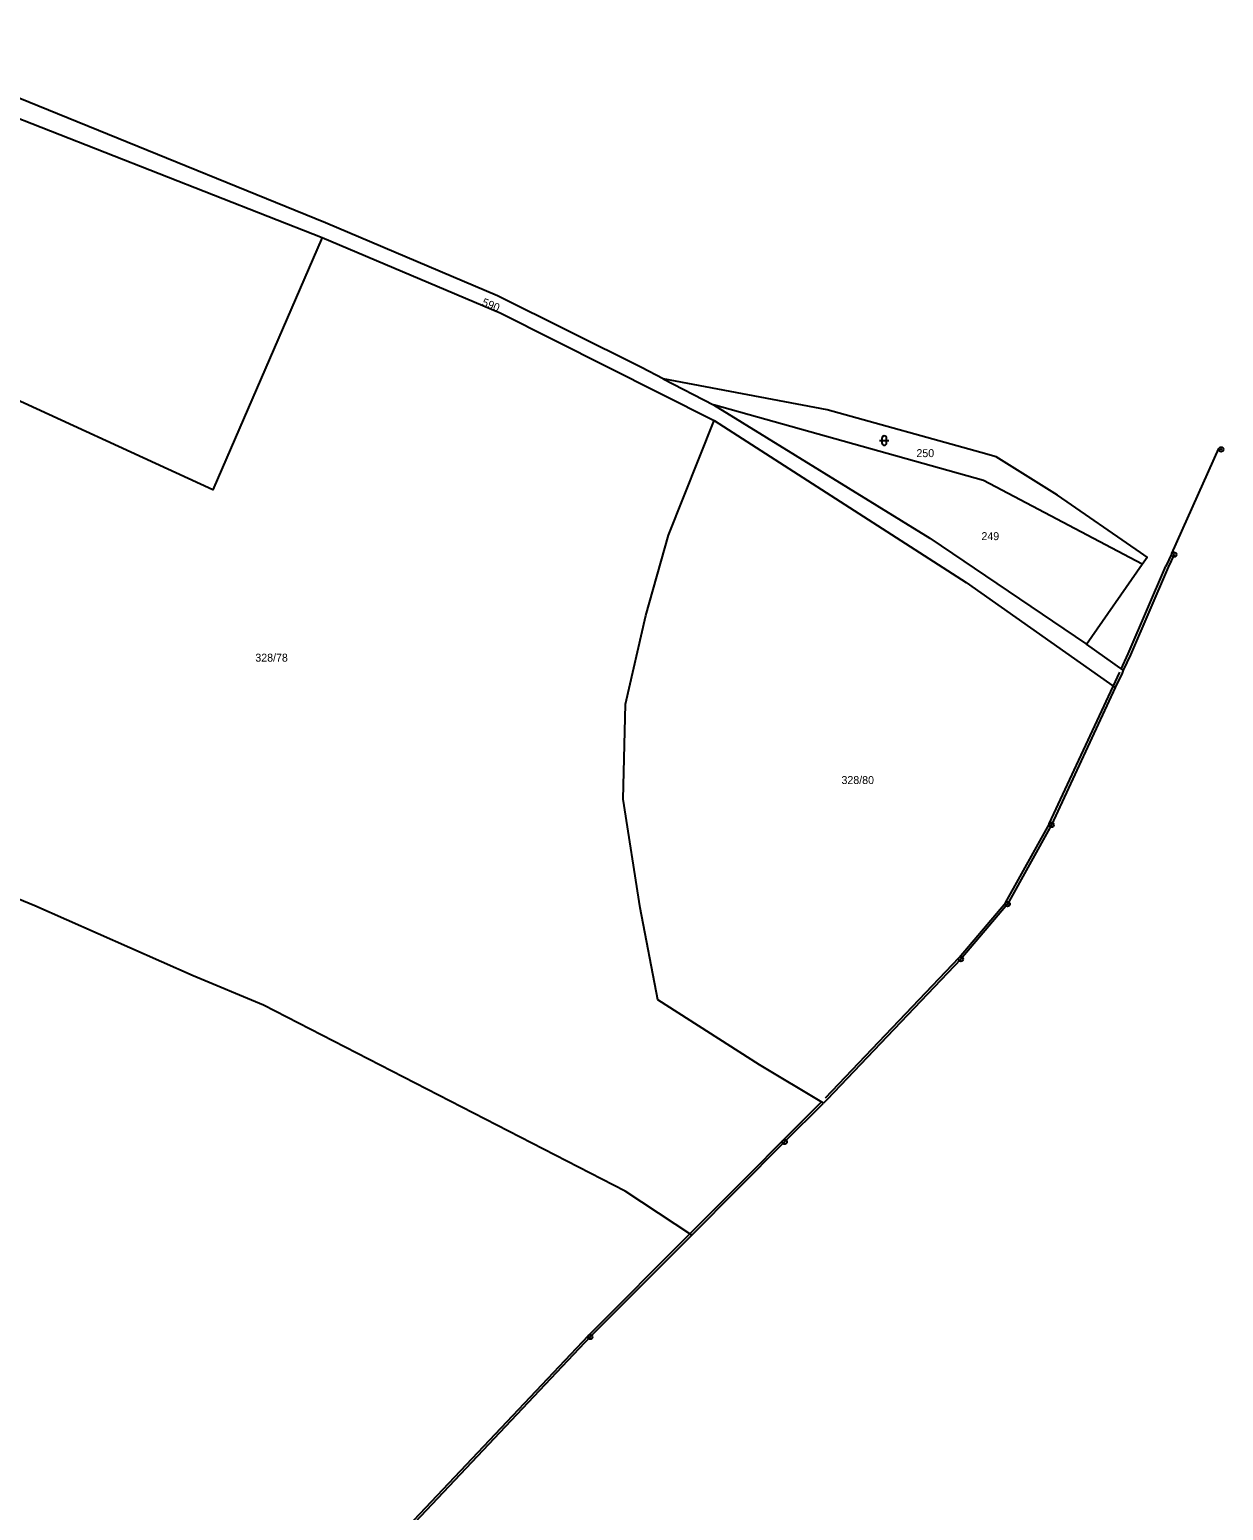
# Model space of a CAD drawing. Extents: x -783948 to -781889, y -1005870 to -1004430.
# Drawn here: x -782144.9 to -781889.5, y -1004993.6 to -1004676.7 of the extents above; entities that cross this region are included whole.
import ezdxf

# ---------------------------------------------------------------- set-up
doc = ezdxf.new("R2010")
doc.units = 0
for name, color, linetype in [('Vrstva 1', 7, 'Continuous'), ('Vrstva 2', 7, 'Continuous'), ('Vrstva 3', 7, 'Continuous'), ('Vrstva 4', 7, 'Continuous'), ('Vrstva 8', 7, 'Continuous')]:
    doc.layers.add(name, color=color, linetype=linetype)

msp = doc.modelspace()

# ---------------------------------------------------------------- linework, layer by layer
at = {"layer": 'Vrstva 1'}
for p, q in [((-782185.46, -1004680.64), (-782082.31, -1004721.17)), ((-782013.96, -1004748.97), (-782044.78, -1004733.61)), ((-782009.35, -1004751.37), (-782013.96, -1004748.97)), ((-781974.24, -1004758.03), (-782009.35, -1004751.37)), ((-782009.35, -1004751.37), (-781998.56, -1004757)), ((-781941.4, -1004767.18), (-781974.24, -1004758.03)), ((-781907.19, -1004788.58), (-781924.97, -1004776.31)), ((-781900.03, -1004789.01), (-781901.31, -1004791.72)), ((-781918.79, -1004808.2), (-781906.86, -1004791.1)), ((-781901.31, -1004791.72), (-781909.38, -1004810.49)), ((-781910.88, -1004813.76), (-781918.79, -1004808.2)), ((-781909.38, -1004810.49), (-781910.88, -1004813.76)), ((-781912.59, -1004817.45), (-781926.27, -1004846.89)), ((-781945.66, -1004875.6), (-781974.28, -1004905.64)), ((-781974.28, -1004905.64), (-781975.07, -1004906.43))]:
    msp.add_line(p, q, dxfattribs=at)
for points in [[(-782044.78, -1004733.61), (-782081.63, -1004718.02), (-782183.39, -1004676.65)], [(-782082.31, -1004721.17), (-782105.71, -1004775.15), (-782155.81, -1004752.17), (-782181.61, -1004741.36), (-782203.38, -1004734.64), (-782238.61, -1004826.25)], [(-782082.31, -1004721.17), (-782044.2, -1004737.25), (-781998.45, -1004760.29)], [(-781906.86, -1004791.1), (-781940.83, -1004773.19), (-781998.56, -1004757)], [(-781998.56, -1004757), (-781952.3, -1004785.49), (-781918.79, -1004808.2)], [(-781975.07, -1004906.43), (-781988.77, -1004898.24), (-782010.52, -1004884.32), (-782014.29, -1004864.64), (-782017.91, -1004841.38), (-782017.39, -1004821.03), (-782013.03, -1004802.03), (-782008.21, -1004784.86), (-781998.45, -1004760.29)], [(-781998.45, -1004760.29), (-781944.53, -1004794.99), (-781912.59, -1004817.45)], [(-781924.97, -1004776.31), (-781938.12, -1004768.09), (-781941.4, -1004767.18)], [(-781906.86, -1004791.1), (-781905.78, -1004789.55), (-781907.19, -1004788.58)], [(-781910.88, -1004813.76), (-781911.16, -1004814.38), (-781912.59, -1004817.45)], [(-782003.24, -1004934.69), (-782017.49, -1004925.27), (-782094.87, -1004885.47), (-782109.93, -1004879.2), (-782143.79, -1004864.19), (-782203.57, -1004839.7)], [(-781926.27, -1004846.89), (-781935.64, -1004863.83), (-781945.66, -1004875.6)], [(-782003.24, -1004934.69), (-781983.35, -1004914.74), (-781975.07, -1004906.43)], [(-782003.24, -1004934.69), (-782024.99, -1004956.5), (-782066.06, -1005000), (-782107.12, -1005043.65)]]:
    msp.add_lwpolyline(points, dxfattribs=at)
at = {"layer": 'Vrstva 3'}
for p, q in [((-781963.03, -1004764.62), (-781961.03, -1004764.62)), ((-781962.53, -1004764.12), (-781962.53, -1004765.12)), ((-781961.53, -1004765.12), (-781961.53, -1004764.12))]:
    msp.add_line(p, q, dxfattribs=at)
for centre, start, end in [((-781962.03, -1004764.12), 0, 180), ((-781962.03, -1004765.12), 180, 359.9879)]:
    msp.add_arc(centre, 0.5, start, end, dxfattribs=at)
at = {"layer": 'Vrstva 4'}
for p, q in [((-781900.49, -1004788.81), (-781890.43, -1004766.3)), ((-781900.48, -1004788.8), (-781901.76, -1004791.51)), ((-781909.84, -1004810.29), (-781901.77, -1004791.52)), ((-781911.33, -1004813.55), (-781909.83, -1004810.28)), ((-781913.04, -1004817.24), (-781911.61, -1004814.17)), ((-781926.72, -1004846.68), (-781913.04, -1004817.24)), ((-781936.08, -1004863.59), (-781926.71, -1004846.65)), ((-781946.04, -1004875.28), (-781936.02, -1004863.51)), ((-781974.64, -1004905.29), (-781946.02, -1004875.25)), ((-781975.42, -1004906.08), (-781983.7, -1004914.39)), ((-781983.7, -1004914.39), (-781991.05, -1004921.76)), ((-781991.05, -1004921.76), (-782003.59, -1004934.34)), ((-782025.34, -1004956.15), (-782003.59, -1004934.34)), ((-782066.42, -1004999.66), (-782025.35, -1004956.16))]:
    msp.add_line(p, q, dxfattribs=at)
at = {"layer": 'Vrstva 8'}
for centre, radius in [((-781889.97, -1004766.5), 0.5), ((-781889.97, -1004766.5), 0.0303), ((-781900.03, -1004789.01), 0.5), ((-781900.03, -1004789.01), 0.0303), ((-781926.27, -1004846.89), 0.5), ((-781926.27, -1004846.89), 0.0303), ((-781935.64, -1004863.83), 0.5), ((-781935.64, -1004863.83), 0.0303), ((-781945.66, -1004875.6), 0.5), ((-781945.66, -1004875.6), 0.0303), ((-781983.35, -1004914.74), 0.5), ((-781983.35, -1004914.74), 0.0303), ((-782024.99, -1004956.5), 0.5), ((-782024.99, -1004956.5), 0.0303)]:
    msp.add_circle(centre, radius, dxfattribs=at)

# ---------------------------------------------------------------- texts
at = {"layer": 'Vrstva 2'}
msp.add_text('590', height=1.7, rotation=338, dxfattribs=at).set_placement((-782048.27, -1004735.64))
for s, p in [('250', (-781955.15, -1004768.16)), ('249', (-781941.24, -1004785.93)), ('328/78', (-782096.62, -1004811.94)), ('328/80', (-781971.19, -1004838.14))]:
    msp.add_text(s, height=1.7, dxfattribs=at).set_placement(p)

doc.saveas('drawing.dxf')
